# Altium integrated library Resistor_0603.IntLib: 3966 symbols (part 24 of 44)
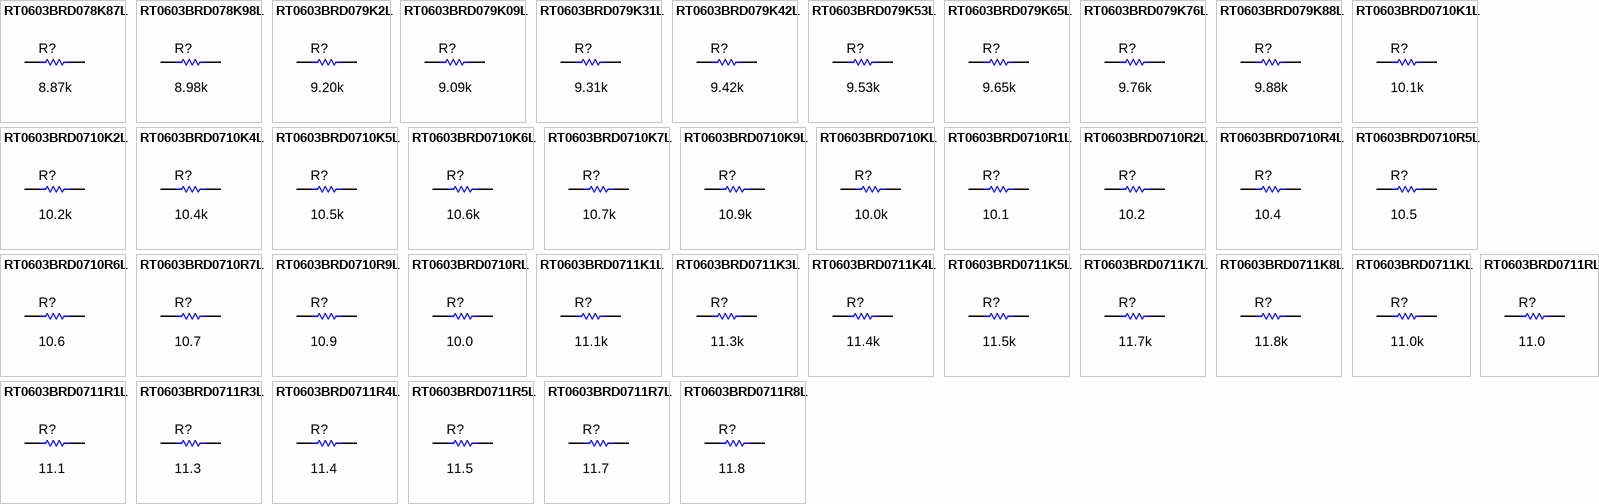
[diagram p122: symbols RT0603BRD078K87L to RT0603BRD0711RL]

## RT0603BRD078K87L
designator R?  ValueDisplayed: 8.87k  (hidden comment: RT0603BRD078K87L)
RES, 8.87 k, 0.1%, 0.1 W, 0603; Manufacturer: Yageo America; CompType: Resistor; Value: 8.87k; Res_ohm: 8870; Value_Code: 8k87; Tolerance_%: 0.1; Value2: 0.1W; VDC_V: 75; TempCo: 25 ppm/C; SizeArea_mm2: 1.28; SizeX_mm: 1.6; SizeY_mm: 0.8; SizeZ_mm: 1; EIA_Code: E192; U/M: EA; AEC Category: Q200
signal-integrity model Resistor
simulation model Resistor
footprint 0603
footprint 0603M
footprint 0603L
footprint 0603_HV
footprint 0603S
pins: 1, 2

## RT0603BRD078K98L
designator R?  ValueDisplayed: 8.98k  (hidden comment: RT0603BRD078K98L)
RES, 8.98 k, 0.1%, 0.1 W, 0603; Manufacturer: Yageo America; CompType: Resistor; Value: 8.98k; Res_ohm: 8980; Value_Code: 8k98; Tolerance_%: 0.1; Value2: 0.1W; VDC_V: 75; TempCo: 25 ppm/C; SizeArea_mm2: 1.28; SizeX_mm: 1.6; SizeY_mm: 0.8; SizeZ_mm: 1; EIA_Code: E192; U/M: EA; AEC Category: Q200
signal-integrity model Resistor
simulation model Resistor
footprint 0603
footprint 0603M
footprint 0603L
footprint 0603_HV
footprint 0603S
pins: 1, 2

## RT0603BRD079K2L
designator R?  ValueDisplayed: 9.20k  (hidden comment: RT0603BRD079K2L)
RES, 9.20 k, 0.1%, 0.1 W, 0603; Manufacturer: Yageo America; CompType: Resistor; Value: 9.20k; Res_ohm: 9200; Value_Code: 9k20; Tolerance_%: 0.1; Value2: 0.1W; VDC_V: 75; TempCo: 25 ppm/C; SizeArea_mm2: 1.28; SizeX_mm: 1.6; SizeY_mm: 0.8; SizeZ_mm: 1; EIA_Code: E192; U/M: EA; AEC Category: Q200
signal-integrity model Resistor
simulation model Resistor
footprint 0603
footprint 0603M
footprint 0603L
footprint 0603_HV
footprint 0603S
pins: 1, 2

## RT0603BRD079K09L
designator R?  ValueDisplayed: 9.09k  (hidden comment: RT0603BRD079K09L)
RES, 9.09 k, 0.1%, 0.1 W, 0603; Manufacturer: Yageo America; CompType: Resistor; Value: 9.09k; Res_ohm: 9090; Value_Code: 9k09; Tolerance_%: 0.1; Value2: 0.1W; VDC_V: 75; TempCo: 25 ppm/C; SizeArea_mm2: 1.28; SizeX_mm: 1.6; SizeY_mm: 0.8; SizeZ_mm: 1; EIA_Code: E192; U/M: EA; AEC Category: Q200
signal-integrity model Resistor
simulation model Resistor
footprint 0603
footprint 0603M
footprint 0603L
footprint 0603_HV
footprint 0603S
pins: 1, 2

## RT0603BRD079K31L
designator R?  ValueDisplayed: 9.31k  (hidden comment: RT0603BRD079K31L)
RES, 9.31 k, 0.1%, 0.1 W, 0603; Manufacturer: Yageo America; CompType: Resistor; Value: 9.31k; Res_ohm: 9310; Value_Code: 9k31; Tolerance_%: 0.1; Value2: 0.1W; VDC_V: 75; TempCo: 25 ppm/C; SizeArea_mm2: 1.28; SizeX_mm: 1.6; SizeY_mm: 0.8; SizeZ_mm: 1; EIA_Code: E192; U/M: EA; AEC Category: Q200
signal-integrity model Resistor
simulation model Resistor
footprint 0603
footprint 0603M
footprint 0603L
footprint 0603_HV
footprint 0603S
pins: 1, 2

## RT0603BRD079K42L
designator R?  ValueDisplayed: 9.42k  (hidden comment: RT0603BRD079K42L)
RES, 9.42 k, 0.1%, 0.1 W, 0603; Manufacturer: Yageo America; CompType: Resistor; Value: 9.42k; Res_ohm: 9420; Value_Code: 9k42; Tolerance_%: 0.1; Value2: 0.1W; VDC_V: 75; TempCo: 25 ppm/C; SizeArea_mm2: 1.28; SizeX_mm: 1.6; SizeY_mm: 0.8; SizeZ_mm: 1; EIA_Code: E192; U/M: EA; AEC Category: Q200
signal-integrity model Resistor
simulation model Resistor
footprint 0603
footprint 0603M
footprint 0603L
footprint 0603_HV
footprint 0603S
pins: 1, 2

## RT0603BRD079K53L
designator R?  ValueDisplayed: 9.53k  (hidden comment: RT0603BRD079K53L)
RES, 9.53 k, 0.1%, 0.1 W, 0603; Manufacturer: Yageo America; CompType: Resistor; Value: 9.53k; Res_ohm: 9530; Value_Code: 9k53; Tolerance_%: 0.1; Value2: 0.1W; VDC_V: 75; TempCo: 25 ppm/C; SizeArea_mm2: 1.28; SizeX_mm: 1.6; SizeY_mm: 0.8; SizeZ_mm: 1; EIA_Code: E192; U/M: EA; AEC Category: Q200
signal-integrity model Resistor
simulation model Resistor
footprint 0603
footprint 0603M
footprint 0603L
footprint 0603_HV
footprint 0603S
pins: 1, 2

## RT0603BRD079K65L
designator R?  ValueDisplayed: 9.65k  (hidden comment: RT0603BRD079K65L)
RES, 9.65 k, 0.1%, 0.1 W, 0603; Manufacturer: Yageo America; CompType: Resistor; Value: 9.65k; Res_ohm: 9650; Value_Code: 9k65; Tolerance_%: 0.1; Value2: 0.1W; VDC_V: 75; TempCo: 25 ppm/C; SizeArea_mm2: 1.28; SizeX_mm: 1.6; SizeY_mm: 0.8; SizeZ_mm: 1; EIA_Code: E192; U/M: EA; AEC Category: Q200
signal-integrity model Resistor
simulation model Resistor
footprint 0603
footprint 0603M
footprint 0603L
footprint 0603_HV
footprint 0603S
pins: 1, 2

## RT0603BRD079K76L
designator R?  ValueDisplayed: 9.76k  (hidden comment: RT0603BRD079K76L)
RES, 9.76 k, 0.1%, 0.1 W, 0603; Manufacturer: Yageo America; CompType: Resistor; Value: 9.76k; Res_ohm: 9760; Value_Code: 9k76; Tolerance_%: 0.1; Value2: 0.1W; VDC_V: 75; TempCo: 25 ppm/C; SizeArea_mm2: 1.28; SizeX_mm: 1.6; SizeY_mm: 0.8; SizeZ_mm: 1; EIA_Code: E192; U/M: EA; AEC Category: Q200
signal-integrity model Resistor
simulation model Resistor
footprint 0603
footprint 0603M
footprint 0603L
footprint 0603_HV
footprint 0603S
pins: 1, 2

## RT0603BRD079K88L
designator R?  ValueDisplayed: 9.88k  (hidden comment: RT0603BRD079K88L)
RES, 9.88 k, 0.1%, 0.1 W, 0603; Manufacturer: Yageo America; CompType: Resistor; Value: 9.88k; Res_ohm: 9880; Value_Code: 9k88; Tolerance_%: 0.1; Value2: 0.1W; VDC_V: 75; TempCo: 25 ppm/C; SizeArea_mm2: 1.28; SizeX_mm: 1.6; SizeY_mm: 0.8; SizeZ_mm: 1; EIA_Code: E192; U/M: EA; AEC Category: Q200
signal-integrity model Resistor
simulation model Resistor
footprint 0603
footprint 0603M
footprint 0603L
footprint 0603_HV
footprint 0603S
pins: 1, 2

## RT0603BRD0710K1L
designator R?  ValueDisplayed: 10.1k  (hidden comment: RT0603BRD0710K1L)
RES, 10.1 k, 0.1%, 0.1 W, 0603; Manufacturer: Yageo America; CompType: Resistor; Value: 10.1k; Res_ohm: 10100; Value_Code: 10k1; Tolerance_%: 0.1; Value2: 0.1W; VDC_V: 75; TempCo: 25 ppm/C; SizeArea_mm2: 1.28; SizeX_mm: 1.6; SizeY_mm: 0.8; SizeZ_mm: 1; EIA_Code: E192; U/M: EA; AEC Category: Q200
signal-integrity model Resistor
simulation model Resistor
footprint 0603
footprint 0603M
footprint 0603L
footprint 0603_HV
footprint 0603S
pins: 1, 2

## RT0603BRD0710K2L
designator R?  ValueDisplayed: 10.2k  (hidden comment: RT0603BRD0710K2L)
RES, 10.2 k, 0.1%, 0.1 W, 0603; Manufacturer: Yageo America; CompType: Resistor; Value: 10.2k; Res_ohm: 10200; Value_Code: 10k2; Tolerance_%: 0.1; Value2: 0.1W; VDC_V: 75; TempCo: 25 ppm/C; SizeArea_mm2: 1.28; SizeX_mm: 1.6; SizeY_mm: 0.8; SizeZ_mm: 1; EIA_Code: E192; U/M: EA; AEC Category: Q200
signal-integrity model Resistor
simulation model Resistor
footprint 0603
footprint 0603M
footprint 0603L
footprint 0603_HV
footprint 0603S
pins: 1, 2

## RT0603BRD0710K4L
designator R?  ValueDisplayed: 10.4k  (hidden comment: RT0603BRD0710K4L)
RES, 10.4 k, 0.1%, 0.1 W, 0603; Manufacturer: Yageo America; CompType: Resistor; Value: 10.4k; Res_ohm: 10400; Value_Code: 10k4; Tolerance_%: 0.1; Value2: 0.1W; VDC_V: 75; TempCo: 25 ppm/C; SizeArea_mm2: 1.28; SizeX_mm: 1.6; SizeY_mm: 0.8; SizeZ_mm: 1; EIA_Code: E192; U/M: EA; AEC Category: Q200
signal-integrity model Resistor
simulation model Resistor
footprint 0603
footprint 0603M
footprint 0603L
footprint 0603_HV
footprint 0603S
pins: 1, 2

## RT0603BRD0710K5L
designator R?  ValueDisplayed: 10.5k  (hidden comment: RT0603BRD0710K5L)
RES, 10.5 k, 0.1%, 0.1 W, 0603; Manufacturer: Yageo America; CompType: Resistor; Value: 10.5k; Res_ohm: 10500; Value_Code: 10k5; Tolerance_%: 0.1; Value2: 0.1W; VDC_V: 75; TempCo: 25 ppm/C; SizeArea_mm2: 1.28; SizeX_mm: 1.6; SizeY_mm: 0.8; SizeZ_mm: 1; EIA_Code: E192; U/M: EA; AEC Category: Q200
signal-integrity model Resistor
simulation model Resistor
footprint 0603
footprint 0603M
footprint 0603L
footprint 0603_HV
footprint 0603S
pins: 1, 2

## RT0603BRD0710K6L
designator R?  ValueDisplayed: 10.6k  (hidden comment: RT0603BRD0710K6L)
RES, 10.6 k, 0.1%, 0.1 W, 0603; Manufacturer: Yageo America; CompType: Resistor; Value: 10.6k; Res_ohm: 10600; Value_Code: 10k6; Tolerance_%: 0.1; Value2: 0.1W; VDC_V: 75; TempCo: 25 ppm/C; SizeArea_mm2: 1.28; SizeX_mm: 1.6; SizeY_mm: 0.8; SizeZ_mm: 1; EIA_Code: E192; U/M: EA; AEC Category: Q200
signal-integrity model Resistor
simulation model Resistor
footprint 0603
footprint 0603M
footprint 0603L
footprint 0603_HV
footprint 0603S
pins: 1, 2

## RT0603BRD0710K7L
designator R?  ValueDisplayed: 10.7k  (hidden comment: RT0603BRD0710K7L)
RES, 10.7 k, 0.1%, 0.1 W, 0603; Manufacturer: Yageo America; CompType: Resistor; Value: 10.7k; Res_ohm: 10700; Value_Code: 10k7; Tolerance_%: 0.1; Value2: 0.1W; VDC_V: 75; TempCo: 25 ppm/C; SizeArea_mm2: 1.28; SizeX_mm: 1.6; SizeY_mm: 0.8; SizeZ_mm: 1; EIA_Code: E192; U/M: EA; AEC Category: Q200
signal-integrity model Resistor
simulation model Resistor
footprint 0603
footprint 0603M
footprint 0603L
footprint 0603_HV
footprint 0603S
pins: 1, 2

## RT0603BRD0710K9L
designator R?  ValueDisplayed: 10.9k  (hidden comment: RT0603BRD0710K9L)
RES, 10.9 k, 0.1%, 0.1 W, 0603; Manufacturer: Yageo America; CompType: Resistor; Value: 10.9k; Res_ohm: 10900; Value_Code: 10k9; Tolerance_%: 0.1; Value2: 0.1W; VDC_V: 75; TempCo: 25 ppm/C; SizeArea_mm2: 1.28; SizeX_mm: 1.6; SizeY_mm: 0.8; SizeZ_mm: 1; EIA_Code: E192; U/M: EA; AEC Category: Q200
signal-integrity model Resistor
simulation model Resistor
footprint 0603
footprint 0603M
footprint 0603L
footprint 0603_HV
footprint 0603S
pins: 1, 2

## RT0603BRD0710KL
designator R?  ValueDisplayed: 10.0k  (hidden comment: RT0603BRD0710KL)
RES, 10.0 k, 0.1%, 0.1 W, 0603; Manufacturer: Yageo America; CompType: Resistor; Value: 10.0k; Res_ohm: 10000; Value_Code: 10k0; Tolerance_%: 0.1; Value2: 0.1W; VDC_V: 75; TempCo: 25 ppm/C; SizeArea_mm2: 1.28; SizeX_mm: 1.6; SizeY_mm: 0.8; SizeZ_mm: 1; EIA_Code: E192; U/M: EA; AEC Category: Q200; Green_Lifecycle: Active; Green_REACh: Passed
signal-integrity model Resistor
simulation model Resistor
footprint 0603
footprint 0603M
footprint 0603L
footprint 0603_HV
footprint 0603S
pins: 1, 2

## RT0603BRD0710R1L
designator R?  ValueDisplayed: 10.1  (hidden comment: RT0603BRD0710R1L)
RES, 10.1, 0.1%, 0.1 W, 0603; Manufacturer: Yageo America; CompType: Resistor; Value: 10.1; Value_Code: 10R1; Tolerance_%: 0.1; Value2: 0.1W; VDC_V: 75; TempCo: 25 ppm/C; SizeArea_mm2: 1.28; SizeX_mm: 1.6; SizeY_mm: 0.8; SizeZ_mm: 1; EIA_Code: E192; U/M: EA; AEC Category: Q200
signal-integrity model Resistor
simulation model Resistor
footprint 0603
footprint 0603M
footprint 0603L
footprint 0603_HV
footprint 0603S
pins: 1, 2

## RT0603BRD0710R2L
designator R?  ValueDisplayed: 10.2  (hidden comment: RT0603BRD0710R2L)
RES, 10.2, 0.1%, 0.1 W, 0603; Manufacturer: Yageo America; CompType: Resistor; Value: 10.2; Value_Code: 10R2; Tolerance_%: 0.1; Value2: 0.1W; VDC_V: 75; TempCo: 25 ppm/C; SizeArea_mm2: 1.28; SizeX_mm: 1.6; SizeY_mm: 0.8; SizeZ_mm: 1; EIA_Code: E192; U/M: EA; AEC Category: Q200
signal-integrity model Resistor
simulation model Resistor
footprint 0603
footprint 0603M
footprint 0603L
footprint 0603_HV
footprint 0603S
pins: 1, 2

## RT0603BRD0710R4L
designator R?  ValueDisplayed: 10.4  (hidden comment: RT0603BRD0710R4L)
RES, 10.4, 0.1%, 0.1 W, 0603; Manufacturer: Yageo America; CompType: Resistor; Value: 10.4; Value_Code: 10R4; Tolerance_%: 0.1; Value2: 0.1W; VDC_V: 75; TempCo: 25 ppm/C; SizeArea_mm2: 1.28; SizeX_mm: 1.6; SizeY_mm: 0.8; SizeZ_mm: 1; EIA_Code: E192; U/M: EA; AEC Category: Q200
signal-integrity model Resistor
simulation model Resistor
footprint 0603
footprint 0603M
footprint 0603L
footprint 0603_HV
footprint 0603S
pins: 1, 2

## RT0603BRD0710R5L
designator R?  ValueDisplayed: 10.5  (hidden comment: RT0603BRD0710R5L)
RES, 10.5, 0.1%, 0.1 W, 0603; Manufacturer: Yageo America; CompType: Resistor; Value: 10.5; Value_Code: 10R5; Tolerance_%: 0.1; Value2: 0.1W; VDC_V: 75; TempCo: 25 ppm/C; SizeArea_mm2: 1.28; SizeX_mm: 1.6; SizeY_mm: 0.8; SizeZ_mm: 1; EIA_Code: E192; U/M: EA; AEC Category: Q200
signal-integrity model Resistor
simulation model Resistor
footprint 0603
footprint 0603M
footprint 0603L
footprint 0603_HV
footprint 0603S
pins: 1, 2

## RT0603BRD0710R6L
designator R?  ValueDisplayed: 10.6  (hidden comment: RT0603BRD0710R6L)
RES, 10.6, 0.1%, 0.1 W, 0603; Manufacturer: Yageo America; CompType: Resistor; Value: 10.6; Value_Code: 10R6; Tolerance_%: 0.1; Value2: 0.1W; VDC_V: 75; TempCo: 25 ppm/C; SizeArea_mm2: 1.28; SizeX_mm: 1.6; SizeY_mm: 0.8; SizeZ_mm: 1; EIA_Code: E192; U/M: EA; AEC Category: Q200
signal-integrity model Resistor
simulation model Resistor
footprint 0603
footprint 0603M
footprint 0603L
footprint 0603_HV
footprint 0603S
pins: 1, 2

## RT0603BRD0710R7L
designator R?  ValueDisplayed: 10.7  (hidden comment: RT0603BRD0710R7L)
RES, 10.7, 0.1%, 0.1 W, 0603; Manufacturer: Yageo America; CompType: Resistor; Value: 10.7; Value_Code: 10R7; Tolerance_%: 0.1; Value2: 0.1W; VDC_V: 75; TempCo: 25 ppm/C; SizeArea_mm2: 1.28; SizeX_mm: 1.6; SizeY_mm: 0.8; SizeZ_mm: 1; EIA_Code: E192; U/M: EA; AEC Category: Q200
signal-integrity model Resistor
simulation model Resistor
footprint 0603
footprint 0603M
footprint 0603L
footprint 0603_HV
footprint 0603S
pins: 1, 2

## RT0603BRD0710R9L
designator R?  ValueDisplayed: 10.9  (hidden comment: RT0603BRD0710R9L)
RES, 10.9, 0.1%, 0.1 W, 0603; Manufacturer: Yageo America; CompType: Resistor; Value: 10.9; Value_Code: 10R9; Tolerance_%: 0.1; Value2: 0.1W; VDC_V: 75; TempCo: 25 ppm/C; SizeArea_mm2: 1.28; SizeX_mm: 1.6; SizeY_mm: 0.8; SizeZ_mm: 1; EIA_Code: E192; U/M: EA; AEC Category: Q200
signal-integrity model Resistor
simulation model Resistor
footprint 0603
footprint 0603M
footprint 0603L
footprint 0603_HV
footprint 0603S
pins: 1, 2

## RT0603BRD0710RL
designator R?  ValueDisplayed: 10.0  (hidden comment: RT0603BRD0710RL)
RES, 10.0, 0.1%, 0.1 W, 0603; Manufacturer: Yageo America; CompType: Resistor; Value: 10.0; Res_ohm: 10; Value_Code: 10R0; Tolerance_%: 0.1; Value2: 0.1W; VDC_V: 75; TempCo: 25 ppm/C; SizeArea_mm2: 1.28; SizeX_mm: 1.6; SizeY_mm: 0.8; SizeZ_mm: 1; EIA_Code: E192; U/M: EA; AEC Category: Q200; Green_Lifecycle: Active; Green_REACh: Passed
signal-integrity model Resistor
simulation model Resistor
footprint 0603
footprint 0603M
footprint 0603L
footprint 0603_HV
footprint 0603S
pins: 1, 2

## RT0603BRD0711K1L
designator R?  ValueDisplayed: 11.1k  (hidden comment: RT0603BRD0711K1L)
RES, 11.1 k, 0.1%, 0.1 W, 0603; Manufacturer: Yageo America; CompType: Resistor; Value: 11.1k; Res_ohm: 11100; Value_Code: 11k1; Tolerance_%: 0.1; Value2: 0.1W; VDC_V: 75; TempCo: 25 ppm/C; SizeArea_mm2: 1.28; SizeX_mm: 1.6; SizeY_mm: 0.8; SizeZ_mm: 1; EIA_Code: E192; U/M: EA; AEC Category: Q200
signal-integrity model Resistor
simulation model Resistor
footprint 0603
footprint 0603M
footprint 0603L
footprint 0603_HV
footprint 0603S
pins: 1, 2

## RT0603BRD0711K3L
designator R?  ValueDisplayed: 11.3k  (hidden comment: RT0603BRD0711K3L)
RES, 11.3 k, 0.1%, 0.1 W, 0603; Manufacturer: Yageo America; CompType: Resistor; Value: 11.3k; Res_ohm: 11300; Value_Code: 11k3; Tolerance_%: 0.1; Value2: 0.1W; VDC_V: 75; TempCo: 25 ppm/C; SizeArea_mm2: 1.28; SizeX_mm: 1.6; SizeY_mm: 0.8; SizeZ_mm: 1; EIA_Code: E192; U/M: EA; AEC Category: Q200
signal-integrity model Resistor
simulation model Resistor
footprint 0603
footprint 0603M
footprint 0603L
footprint 0603_HV
footprint 0603S
pins: 1, 2

## RT0603BRD0711K4L
designator R?  ValueDisplayed: 11.4k  (hidden comment: RT0603BRD0711K4L)
RES, 11.4 k, 0.1%, 0.1 W, 0603; Manufacturer: Yageo America; CompType: Resistor; Value: 11.4k; Res_ohm: 11400; Value_Code: 11k4; Tolerance_%: 0.1; Value2: 0.1W; VDC_V: 75; TempCo: 25 ppm/C; SizeArea_mm2: 1.28; SizeX_mm: 1.6; SizeY_mm: 0.8; SizeZ_mm: 1; EIA_Code: E192; U/M: EA; AEC Category: Q200
signal-integrity model Resistor
simulation model Resistor
footprint 0603
footprint 0603M
footprint 0603L
footprint 0603_HV
footprint 0603S
pins: 1, 2

## RT0603BRD0711K5L
designator R?  ValueDisplayed: 11.5k  (hidden comment: RT0603BRD0711K5L)
RES, 11.5 k, 0.1%, 0.1 W, 0603; Manufacturer: Yageo America; CompType: Resistor; Value: 11.5k; Res_ohm: 11500; Value_Code: 11k5; Tolerance_%: 0.1; Value2: 0.1W; VDC_V: 75; TempCo: 25 ppm/C; SizeArea_mm2: 1.28; SizeX_mm: 1.6; SizeY_mm: 0.8; SizeZ_mm: 1; EIA_Code: E192; U/M: EA; AEC Category: Q200
signal-integrity model Resistor
simulation model Resistor
footprint 0603
footprint 0603M
footprint 0603L
footprint 0603_HV
footprint 0603S
pins: 1, 2

## RT0603BRD0711K7L
designator R?  ValueDisplayed: 11.7k  (hidden comment: RT0603BRD0711K7L)
RES, 11.7 k, 0.1%, 0.1 W, 0603; Manufacturer: Yageo America; CompType: Resistor; Value: 11.7k; Res_ohm: 11700; Value_Code: 11k7; Tolerance_%: 0.1; Value2: 0.1W; VDC_V: 75; TempCo: 25 ppm/C; SizeArea_mm2: 1.28; SizeX_mm: 1.6; SizeY_mm: 0.8; SizeZ_mm: 1; EIA_Code: E192; U/M: EA; AEC Category: Q200
signal-integrity model Resistor
simulation model Resistor
footprint 0603
footprint 0603M
footprint 0603L
footprint 0603_HV
footprint 0603S
pins: 1, 2

## RT0603BRD0711K8L
designator R?  ValueDisplayed: 11.8k  (hidden comment: RT0603BRD0711K8L)
RES, 11.8 k, 0.1%, 0.1 W, 0603; Manufacturer: Yageo America; CompType: Resistor; Value: 11.8k; Res_ohm: 11800; Value_Code: 11k8; Tolerance_%: 0.1; Value2: 0.1W; VDC_V: 75; TempCo: 25 ppm/C; SizeArea_mm2: 1.28; SizeX_mm: 1.6; SizeY_mm: 0.8; SizeZ_mm: 1; EIA_Code: E192; U/M: EA; AEC Category: Q200
signal-integrity model Resistor
simulation model Resistor
footprint 0603
footprint 0603M
footprint 0603L
footprint 0603_HV
footprint 0603S
pins: 1, 2

## RT0603BRD0711KL
designator R?  ValueDisplayed: 11.0k  (hidden comment: RT0603BRD0711KL)
RES, 11.0 k, 0.1%, 0.1 W, 0603; Manufacturer: Yageo America; CompType: Resistor; Value: 11.0k; Res_ohm: 11000; Value_Code: 11k0; Tolerance_%: 0.1; Value2: 0.1W; VDC_V: 75; TempCo: 25 ppm/C; SizeArea_mm2: 1.28; SizeX_mm: 1.6; SizeY_mm: 0.8; SizeZ_mm: 1; EIA_Code: E192; U/M: EA; AEC Category: Q200
signal-integrity model Resistor
simulation model Resistor
footprint 0603
footprint 0603M
footprint 0603L
footprint 0603_HV
footprint 0603S
pins: 1, 2

## RT0603BRD0711R1L
designator R?  ValueDisplayed: 11.1  (hidden comment: RT0603BRD0711R1L)
RES, 11.1, 0.1%, 0.1 W, 0603; Manufacturer: Yageo America; CompType: Resistor; Value: 11.1; Value_Code: 11R1; Tolerance_%: 0.1; Value2: 0.1W; VDC_V: 75; TempCo: 25 ppm/C; SizeArea_mm2: 1.28; SizeX_mm: 1.6; SizeY_mm: 0.8; SizeZ_mm: 1; EIA_Code: E192; U/M: EA; AEC Category: Q200
signal-integrity model Resistor
simulation model Resistor
footprint 0603
footprint 0603M
footprint 0603L
footprint 0603_HV
footprint 0603S
pins: 1, 2

## RT0603BRD0711R3L
designator R?  ValueDisplayed: 11.3  (hidden comment: RT0603BRD0711R3L)
RES, 11.3, 0.1%, 0.1 W, 0603; Manufacturer: Yageo America; CompType: Resistor; Value: 11.3; Value_Code: 11R3; Tolerance_%: 0.1; Value2: 0.1W; VDC_V: 75; TempCo: 25 ppm/C; SizeArea_mm2: 1.28; SizeX_mm: 1.6; SizeY_mm: 0.8; SizeZ_mm: 1; EIA_Code: E192; U/M: EA; AEC Category: Q200
signal-integrity model Resistor
simulation model Resistor
footprint 0603
footprint 0603M
footprint 0603L
footprint 0603_HV
footprint 0603S
pins: 1, 2

## RT0603BRD0711R4L
designator R?  ValueDisplayed: 11.4  (hidden comment: RT0603BRD0711R4L)
RES, 11.4, 0.1%, 0.1 W, 0603; Manufacturer: Yageo America; CompType: Resistor; Value: 11.4; Value_Code: 11R4; Tolerance_%: 0.1; Value2: 0.1W; VDC_V: 75; TempCo: 25 ppm/C; SizeArea_mm2: 1.28; SizeX_mm: 1.6; SizeY_mm: 0.8; SizeZ_mm: 1; EIA_Code: E192; U/M: EA; AEC Category: Q200
signal-integrity model Resistor
simulation model Resistor
footprint 0603
footprint 0603M
footprint 0603L
footprint 0603_HV
footprint 0603S
pins: 1, 2

## RT0603BRD0711R5L
designator R?  ValueDisplayed: 11.5  (hidden comment: RT0603BRD0711R5L)
RES, 11.5, 0.1%, 0.1 W, 0603; Manufacturer: Yageo America; CompType: Resistor; Value: 11.5; Value_Code: 11R5; Tolerance_%: 0.1; Value2: 0.1W; VDC_V: 75; TempCo: 25 ppm/C; SizeArea_mm2: 1.28; SizeX_mm: 1.6; SizeY_mm: 0.8; SizeZ_mm: 1; EIA_Code: E192; U/M: EA; AEC Category: Q200
signal-integrity model Resistor
simulation model Resistor
footprint 0603
footprint 0603M
footprint 0603L
footprint 0603_HV
footprint 0603S
pins: 1, 2

## RT0603BRD0711R7L
designator R?  ValueDisplayed: 11.7  (hidden comment: RT0603BRD0711R7L)
RES, 11.7, 0.1%, 0.1 W, 0603; Manufacturer: Yageo America; CompType: Resistor; Value: 11.7; Value_Code: 11R7; Tolerance_%: 0.1; Value2: 0.1W; VDC_V: 75; TempCo: 25 ppm/C; SizeArea_mm2: 1.28; SizeX_mm: 1.6; SizeY_mm: 0.8; SizeZ_mm: 1; EIA_Code: E192; U/M: EA; AEC Category: Q200
signal-integrity model Resistor
simulation model Resistor
footprint 0603
footprint 0603M
footprint 0603L
footprint 0603_HV
footprint 0603S
pins: 1, 2

## RT0603BRD0711R8L
designator R?  ValueDisplayed: 11.8  (hidden comment: RT0603BRD0711R8L)
RES, 11.8, 0.1%, 0.1 W, 0603; Manufacturer: Yageo America; CompType: Resistor; Value: 11.8; Value_Code: 11R8; Tolerance_%: 0.1; Value2: 0.1W; VDC_V: 75; TempCo: 25 ppm/C; SizeArea_mm2: 1.28; SizeX_mm: 1.6; SizeY_mm: 0.8; SizeZ_mm: 1; EIA_Code: E192; U/M: EA; AEC Category: Q200
signal-integrity model Resistor
simulation model Resistor
footprint 0603
footprint 0603M
footprint 0603L
footprint 0603_HV
footprint 0603S
pins: 1, 2

## RT0603BRD0711RL
designator R?  ValueDisplayed: 11.0  (hidden comment: RT0603BRD0711RL)
RES, 11.0, 0.1%, 0.1 W, 0603; Manufacturer: Yageo America; CompType: Resistor; Value: 11.0; Res_ohm: 11; Value_Code: 11R0; Tolerance_%: 0.1; Value2: 0.1W; VDC_V: 75; TempCo: 25 ppm/C; SizeArea_mm2: 1.28; SizeX_mm: 1.6; SizeY_mm: 0.8; SizeZ_mm: 1; EIA_Code: E192; U/M: EA; AEC Category: Q200
signal-integrity model Resistor
simulation model Resistor
footprint 0603
footprint 0603M
footprint 0603L
footprint 0603_HV
footprint 0603S
pins: 1, 2

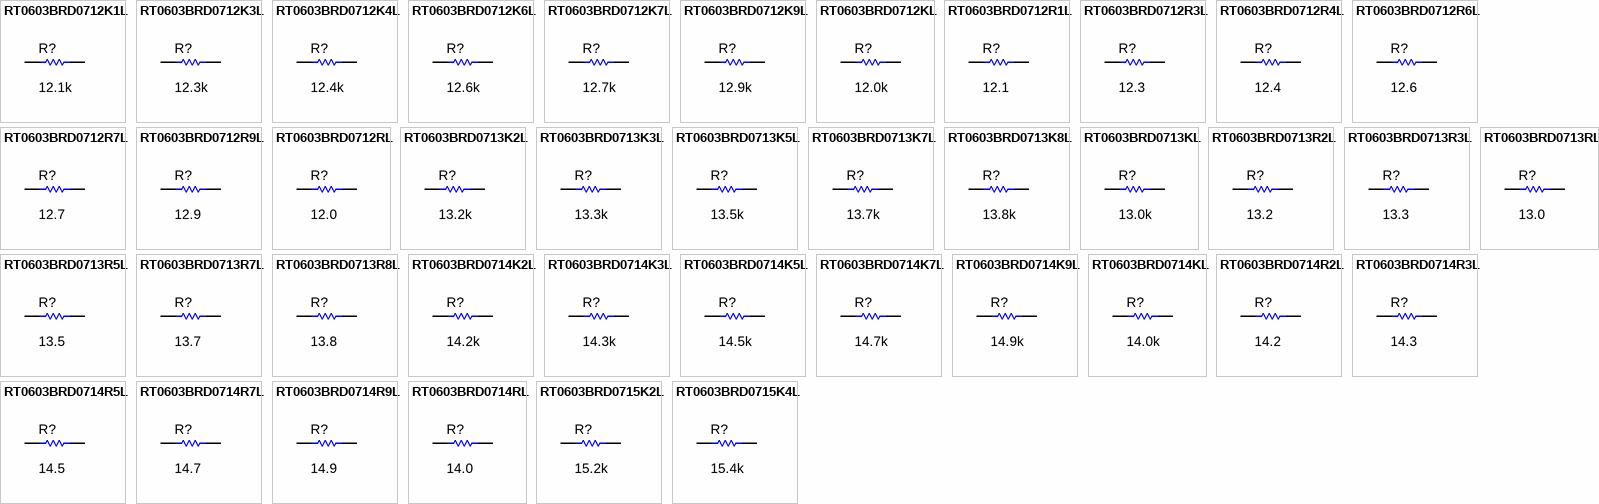
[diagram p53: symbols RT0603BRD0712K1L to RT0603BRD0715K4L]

## RT0603BRD0712K1L
designator R?  ValueDisplayed: 12.1k  (hidden comment: RT0603BRD0712K1L)
RES, 12.1 k, 0.1%, 0.1 W, 0603; Manufacturer: Yageo America; CompType: Resistor; Value: 12.1k; Res_ohm: 12100; Value_Code: 12k1; Tolerance_%: 0.1; Value2: 0.1W; VDC_V: 75; TempCo: 25 ppm/C; SizeArea_mm2: 1.28; SizeX_mm: 1.6; SizeY_mm: 0.8; SizeZ_mm: 1; EIA_Code: E192; U/M: EA; AEC Category: Q200
signal-integrity model Resistor
simulation model Resistor
footprint 0603
footprint 0603M
footprint 0603L
footprint 0603_HV
footprint 0603S
pins: 1, 2

## RT0603BRD0712K3L
designator R?  ValueDisplayed: 12.3k  (hidden comment: RT0603BRD0712K3L)
RES, 12.3 k, 0.1%, 0.1 W, 0603; Manufacturer: Yageo America; CompType: Resistor; Value: 12.3k; Res_ohm: 12300; Value_Code: 12k3; Tolerance_%: 0.1; Value2: 0.1W; VDC_V: 75; TempCo: 25 ppm/C; SizeArea_mm2: 1.28; SizeX_mm: 1.6; SizeY_mm: 0.8; SizeZ_mm: 1; EIA_Code: E192; U/M: EA; AEC Category: Q200
signal-integrity model Resistor
simulation model Resistor
footprint 0603
footprint 0603M
footprint 0603L
footprint 0603_HV
footprint 0603S
pins: 1, 2

## RT0603BRD0712K4L
designator R?  ValueDisplayed: 12.4k  (hidden comment: RT0603BRD0712K4L)
RES, 12.4 k, 0.1%, 0.1 W, 0603; Manufacturer: Yageo America; CompType: Resistor; Value: 12.4k; Res_ohm: 12400; Value_Code: 12k4; Tolerance_%: 0.1; Value2: 0.1W; VDC_V: 75; TempCo: 25 ppm/C; SizeArea_mm2: 1.28; SizeX_mm: 1.6; SizeY_mm: 0.8; SizeZ_mm: 1; EIA_Code: E192; U/M: EA; AEC Category: Q200
signal-integrity model Resistor
simulation model Resistor
footprint 0603
footprint 0603M
footprint 0603L
footprint 0603_HV
footprint 0603S
pins: 1, 2

## RT0603BRD0712K6L
designator R?  ValueDisplayed: 12.6k  (hidden comment: RT0603BRD0712K6L)
RES, 12.6 k, 0.1%, 0.1 W, 0603; Manufacturer: Yageo America; CompType: Resistor; Value: 12.6k; Res_ohm: 12600; Value_Code: 12k6; Tolerance_%: 0.1; Value2: 0.1W; VDC_V: 75; TempCo: 25 ppm/C; SizeArea_mm2: 1.28; SizeX_mm: 1.6; SizeY_mm: 0.8; SizeZ_mm: 1; EIA_Code: E192; U/M: EA; AEC Category: Q200
signal-integrity model Resistor
simulation model Resistor
footprint 0603
footprint 0603M
footprint 0603L
footprint 0603_HV
footprint 0603S
pins: 1, 2

## RT0603BRD0712K7L
designator R?  ValueDisplayed: 12.7k  (hidden comment: RT0603BRD0712K7L)
RES, 12.7 k, 0.1%, 0.1 W, 0603; Manufacturer: Yageo America; CompType: Resistor; Value: 12.7k; Res_ohm: 12700; Value_Code: 12k7; Tolerance_%: 0.1; Value2: 0.1W; VDC_V: 75; TempCo: 25 ppm/C; SizeArea_mm2: 1.28; SizeX_mm: 1.6; SizeY_mm: 0.8; SizeZ_mm: 1; EIA_Code: E192; U/M: EA; AEC Category: Q200
signal-integrity model Resistor
simulation model Resistor
footprint 0603
footprint 0603M
footprint 0603L
footprint 0603_HV
footprint 0603S
pins: 1, 2

## RT0603BRD0712K9L
designator R?  ValueDisplayed: 12.9k  (hidden comment: RT0603BRD0712K9L)
RES, 12.9 k, 0.1%, 0.1 W, 0603; Manufacturer: Yageo America; CompType: Resistor; Value: 12.9k; Res_ohm: 12900; Value_Code: 12k9; Tolerance_%: 0.1; Value2: 0.1W; VDC_V: 75; TempCo: 25 ppm/C; SizeArea_mm2: 1.28; SizeX_mm: 1.6; SizeY_mm: 0.8; SizeZ_mm: 1; EIA_Code: E192; U/M: EA; AEC Category: Q200
signal-integrity model Resistor
simulation model Resistor
footprint 0603
footprint 0603M
footprint 0603L
footprint 0603_HV
footprint 0603S
pins: 1, 2

## RT0603BRD0712KL
designator R?  ValueDisplayed: 12.0k  (hidden comment: RT0603BRD0712KL)
RES, 12.0 k, 0.1%, 0.1 W, 0603; Manufacturer: Yageo America; CompType: Resistor; Value: 12.0k; Res_ohm: 12000; Value_Code: 12k0; Tolerance_%: 0.1; Value2: 0.1W; VDC_V: 75; TempCo: 25 ppm/C; SizeArea_mm2: 1.28; SizeX_mm: 1.6; SizeY_mm: 0.8; SizeZ_mm: 1; EIA_Code: E192; U/M: EA; AEC Category: Q200
signal-integrity model Resistor
simulation model Resistor
footprint 0603
footprint 0603M
footprint 0603L
footprint 0603_HV
footprint 0603S
pins: 1, 2

## RT0603BRD0712R1L
designator R?  ValueDisplayed: 12.1  (hidden comment: RT0603BRD0712R1L)
RES, 12.1, 0.1%, 0.1 W, 0603; Manufacturer: Yageo America; CompType: Resistor; Value: 12.1; Value_Code: 12R1; Tolerance_%: 0.1; Value2: 0.1W; VDC_V: 75; TempCo: 25 ppm/C; SizeArea_mm2: 1.28; SizeX_mm: 1.6; SizeY_mm: 0.8; SizeZ_mm: 1; EIA_Code: E192; U/M: EA; AEC Category: Q200
signal-integrity model Resistor
simulation model Resistor
footprint 0603
footprint 0603M
footprint 0603L
footprint 0603_HV
footprint 0603S
pins: 1, 2

## RT0603BRD0712R3L
designator R?  ValueDisplayed: 12.3  (hidden comment: RT0603BRD0712R3L)
RES, 12.3, 0.1%, 0.1 W, 0603; Manufacturer: Yageo America; CompType: Resistor; Value: 12.3; Value_Code: 12R3; Tolerance_%: 0.1; Value2: 0.1W; VDC_V: 75; TempCo: 25 ppm/C; SizeArea_mm2: 1.28; SizeX_mm: 1.6; SizeY_mm: 0.8; SizeZ_mm: 1; EIA_Code: E192; U/M: EA; AEC Category: Q200
signal-integrity model Resistor
simulation model Resistor
footprint 0603
footprint 0603M
footprint 0603L
footprint 0603_HV
footprint 0603S
pins: 1, 2

## RT0603BRD0712R4L
designator R?  ValueDisplayed: 12.4  (hidden comment: RT0603BRD0712R4L)
RES, 12.4, 0.1%, 0.1 W, 0603; Manufacturer: Yageo America; CompType: Resistor; Value: 12.4; Value_Code: 12R4; Tolerance_%: 0.1; Value2: 0.1W; VDC_V: 75; TempCo: 25 ppm/C; SizeArea_mm2: 1.28; SizeX_mm: 1.6; SizeY_mm: 0.8; SizeZ_mm: 1; EIA_Code: E192; U/M: EA; AEC Category: Q200
signal-integrity model Resistor
simulation model Resistor
footprint 0603
footprint 0603M
footprint 0603L
footprint 0603_HV
footprint 0603S
pins: 1, 2

## RT0603BRD0712R6L
designator R?  ValueDisplayed: 12.6  (hidden comment: RT0603BRD0712R6L)
RES, 12.6, 0.1%, 0.1 W, 0603; Manufacturer: Yageo America; CompType: Resistor; Value: 12.6; Value_Code: 12R6; Tolerance_%: 0.1; Value2: 0.1W; VDC_V: 75; TempCo: 25 ppm/C; SizeArea_mm2: 1.28; SizeX_mm: 1.6; SizeY_mm: 0.8; SizeZ_mm: 1; EIA_Code: E192; U/M: EA; AEC Category: Q200
signal-integrity model Resistor
simulation model Resistor
footprint 0603
footprint 0603M
footprint 0603L
footprint 0603_HV
footprint 0603S
pins: 1, 2

## RT0603BRD0712R7L
designator R?  ValueDisplayed: 12.7  (hidden comment: RT0603BRD0712R7L)
RES, 12.7, 0.1%, 0.1 W, 0603; Manufacturer: Yageo America; CompType: Resistor; Value: 12.7; Value_Code: 12R7; Tolerance_%: 0.1; Value2: 0.1W; VDC_V: 75; TempCo: 25 ppm/C; SizeArea_mm2: 1.28; SizeX_mm: 1.6; SizeY_mm: 0.8; SizeZ_mm: 1; EIA_Code: E192; U/M: EA; AEC Category: Q200
signal-integrity model Resistor
simulation model Resistor
footprint 0603
footprint 0603M
footprint 0603L
footprint 0603_HV
footprint 0603S
pins: 1, 2

## RT0603BRD0712R9L
designator R?  ValueDisplayed: 12.9  (hidden comment: RT0603BRD0712R9L)
RES, 12.9, 0.1%, 0.1 W, 0603; Manufacturer: Yageo America; CompType: Resistor; Value: 12.9; Value_Code: 12R9; Tolerance_%: 0.1; Value2: 0.1W; VDC_V: 75; TempCo: 25 ppm/C; SizeArea_mm2: 1.28; SizeX_mm: 1.6; SizeY_mm: 0.8; SizeZ_mm: 1; EIA_Code: E192; U/M: EA; AEC Category: Q200
signal-integrity model Resistor
simulation model Resistor
footprint 0603
footprint 0603M
footprint 0603L
footprint 0603_HV
footprint 0603S
pins: 1, 2

## RT0603BRD0712RL
designator R?  ValueDisplayed: 12.0  (hidden comment: RT0603BRD0712RL)
RES, 12.0, 0.1%, 0.1 W, 0603; Manufacturer: Yageo America; CompType: Resistor; Value: 12.0; Res_ohm: 12; Value_Code: 12R0; Tolerance_%: 0.1; Value2: 0.1W; VDC_V: 75; TempCo: 25 ppm/C; SizeArea_mm2: 1.28; SizeX_mm: 1.6; SizeY_mm: 0.8; SizeZ_mm: 1; EIA_Code: E192; U/M: EA; AEC Category: Q200
signal-integrity model Resistor
simulation model Resistor
footprint 0603
footprint 0603M
footprint 0603L
footprint 0603_HV
footprint 0603S
pins: 1, 2

## RT0603BRD0713K2L
designator R?  ValueDisplayed: 13.2k  (hidden comment: RT0603BRD0713K2L)
RES, 13.2 k, 0.1%, 0.1 W, 0603; Manufacturer: Yageo America; CompType: Resistor; Value: 13.2k; Res_ohm: 13200; Value_Code: 13k2; Tolerance_%: 0.1; Value2: 0.1W; VDC_V: 75; TempCo: 25 ppm/C; SizeArea_mm2: 1.28; SizeX_mm: 1.6; SizeY_mm: 0.8; SizeZ_mm: 1; EIA_Code: E192; U/M: EA; AEC Category: Q200
signal-integrity model Resistor
simulation model Resistor
footprint 0603
footprint 0603M
footprint 0603L
footprint 0603_HV
footprint 0603S
pins: 1, 2

## RT0603BRD0713K3L
designator R?  ValueDisplayed: 13.3k  (hidden comment: RT0603BRD0713K3L)
RES, 13.3 k, 0.1%, 0.1 W, 0603; Manufacturer: Yageo America; CompType: Resistor; Value: 13.3k; Res_ohm: 13300; Value_Code: 13k3; Tolerance_%: 0.1; Value2: 0.1W; VDC_V: 75; TempCo: 25 ppm/C; SizeArea_mm2: 1.28; SizeX_mm: 1.6; SizeY_mm: 0.8; SizeZ_mm: 1; EIA_Code: E192; U/M: EA; AEC Category: Q200
signal-integrity model Resistor
simulation model Resistor
footprint 0603
footprint 0603M
footprint 0603L
footprint 0603_HV
footprint 0603S
pins: 1, 2

## RT0603BRD0713K5L
designator R?  ValueDisplayed: 13.5k  (hidden comment: RT0603BRD0713K5L)
RES, 13.5 k, 0.1%, 0.1 W, 0603; Manufacturer: Yageo America; CompType: Resistor; Value: 13.5k; Res_ohm: 13500; Value_Code: 13k5; Tolerance_%: 0.1; Value2: 0.1W; VDC_V: 75; TempCo: 25 ppm/C; SizeArea_mm2: 1.28; SizeX_mm: 1.6; SizeY_mm: 0.8; SizeZ_mm: 1; EIA_Code: E192; U/M: EA; AEC Category: Q200
signal-integrity model Resistor
simulation model Resistor
footprint 0603
footprint 0603M
footprint 0603L
footprint 0603_HV
footprint 0603S
pins: 1, 2

## RT0603BRD0713K7L
designator R?  ValueDisplayed: 13.7k  (hidden comment: RT0603BRD0713K7L)
RES, 13.7 k, 0.1%, 0.1 W, 0603; Manufacturer: Yageo America; CompType: Resistor; Value: 13.7k; Res_ohm: 13700; Value_Code: 13k7; Tolerance_%: 0.1; Value2: 0.1W; VDC_V: 75; TempCo: 25 ppm/C; SizeArea_mm2: 1.28; SizeX_mm: 1.6; SizeY_mm: 0.8; SizeZ_mm: 1; EIA_Code: E192; U/M: EA; AEC Category: Q200
signal-integrity model Resistor
simulation model Resistor
footprint 0603
footprint 0603M
footprint 0603L
footprint 0603_HV
footprint 0603S
pins: 1, 2

## RT0603BRD0713K8L
designator R?  ValueDisplayed: 13.8k  (hidden comment: RT0603BRD0713K8L)
RES, 13.8 k, 0.1%, 0.1 W, 0603; Manufacturer: Yageo America; CompType: Resistor; Value: 13.8k; Res_ohm: 13800; Value_Code: 13k8; Tolerance_%: 0.1; Value2: 0.1W; VDC_V: 75; TempCo: 25 ppm/C; SizeArea_mm2: 1.28; SizeX_mm: 1.6; SizeY_mm: 0.8; SizeZ_mm: 1; EIA_Code: E192; U/M: EA; AEC Category: Q200
signal-integrity model Resistor
simulation model Resistor
footprint 0603
footprint 0603M
footprint 0603L
footprint 0603_HV
footprint 0603S
pins: 1, 2

## RT0603BRD0713KL
designator R?  ValueDisplayed: 13.0k  (hidden comment: RT0603BRD0713KL)
RES, 13.0 k, 0.1%, 0.1 W, 0603; Manufacturer: Yageo America; CompType: Resistor; Value: 13.0k; Res_ohm: 13000; Value_Code: 13k0; Tolerance_%: 0.1; Value2: 0.1W; VDC_V: 75; TempCo: 25 ppm/C; SizeArea_mm2: 1.28; SizeX_mm: 1.6; SizeY_mm: 0.8; SizeZ_mm: 1; EIA_Code: E192; U/M: EA; AEC Category: Q200
signal-integrity model Resistor
simulation model Resistor
footprint 0603
footprint 0603M
footprint 0603L
footprint 0603_HV
footprint 0603S
pins: 1, 2

## RT0603BRD0713R2L
designator R?  ValueDisplayed: 13.2  (hidden comment: RT0603BRD0713R2L)
RES, 13.2, 0.1%, 0.1 W, 0603; Manufacturer: Yageo America; CompType: Resistor; Value: 13.2; Value_Code: 13R2; Tolerance_%: 0.1; Value2: 0.1W; VDC_V: 75; TempCo: 25 ppm/C; SizeArea_mm2: 1.28; SizeX_mm: 1.6; SizeY_mm: 0.8; SizeZ_mm: 1; EIA_Code: E192; U/M: EA; AEC Category: Q200
signal-integrity model Resistor
simulation model Resistor
footprint 0603
footprint 0603M
footprint 0603L
footprint 0603_HV
footprint 0603S
pins: 1, 2

## RT0603BRD0713R3L
designator R?  ValueDisplayed: 13.3  (hidden comment: RT0603BRD0713R3L)
RES, 13.3, 0.1%, 0.1 W, 0603; Manufacturer: Yageo America; CompType: Resistor; Value: 13.3; Value_Code: 13R3; Tolerance_%: 0.1; Value2: 0.1W; VDC_V: 75; TempCo: 25 ppm/C; SizeArea_mm2: 1.28; SizeX_mm: 1.6; SizeY_mm: 0.8; SizeZ_mm: 1; EIA_Code: E192; U/M: EA; AEC Category: Q200
signal-integrity model Resistor
simulation model Resistor
footprint 0603
footprint 0603M
footprint 0603L
footprint 0603_HV
footprint 0603S
pins: 1, 2

## RT0603BRD0713R5L
designator R?  ValueDisplayed: 13.5  (hidden comment: RT0603BRD0713R5L)
RES, 13.5, 0.1%, 0.1 W, 0603; Manufacturer: Yageo America; CompType: Resistor; Value: 13.5; Value_Code: 13R5; Tolerance_%: 0.1; Value2: 0.1W; VDC_V: 75; TempCo: 25 ppm/C; SizeArea_mm2: 1.28; SizeX_mm: 1.6; SizeY_mm: 0.8; SizeZ_mm: 1; EIA_Code: E192; U/M: EA; AEC Category: Q200
signal-integrity model Resistor
simulation model Resistor
footprint 0603
footprint 0603M
footprint 0603L
footprint 0603_HV
footprint 0603S
pins: 1, 2

## RT0603BRD0713R7L
designator R?  ValueDisplayed: 13.7  (hidden comment: RT0603BRD0713R7L)
RES, 13.7, 0.1%, 0.1 W, 0603; Manufacturer: Yageo America; CompType: Resistor; Value: 13.7; Value_Code: 13R7; Tolerance_%: 0.1; Value2: 0.1W; VDC_V: 75; TempCo: 25 ppm/C; SizeArea_mm2: 1.28; SizeX_mm: 1.6; SizeY_mm: 0.8; SizeZ_mm: 1; EIA_Code: E192; U/M: EA; AEC Category: Q200
signal-integrity model Resistor
simulation model Resistor
footprint 0603
footprint 0603M
footprint 0603L
footprint 0603_HV
footprint 0603S
pins: 1, 2

## RT0603BRD0713R8L
designator R?  ValueDisplayed: 13.8  (hidden comment: RT0603BRD0713R8L)
RES, 13.8, 0.1%, 0.1 W, 0603; Manufacturer: Yageo America; CompType: Resistor; Value: 13.8; Value_Code: 13R8; Tolerance_%: 0.1; Value2: 0.1W; VDC_V: 75; TempCo: 25 ppm/C; SizeArea_mm2: 1.28; SizeX_mm: 1.6; SizeY_mm: 0.8; SizeZ_mm: 1; EIA_Code: E192; U/M: EA; AEC Category: Q200
signal-integrity model Resistor
simulation model Resistor
footprint 0603
footprint 0603M
footprint 0603L
footprint 0603_HV
footprint 0603S
pins: 1, 2

## RT0603BRD0713RL
designator R?  ValueDisplayed: 13.0  (hidden comment: RT0603BRD0713RL)
RES, 13.0, 0.1%, 0.1 W, 0603; Manufacturer: Yageo America; CompType: Resistor; Value: 13.0; Res_ohm: 13; Value_Code: 13R0; Tolerance_%: 0.1; Value2: 0.1W; VDC_V: 75; TempCo: 25 ppm/C; SizeArea_mm2: 1.28; SizeX_mm: 1.6; SizeY_mm: 0.8; SizeZ_mm: 1; EIA_Code: E192; U/M: EA; AEC Category: Q200
signal-integrity model Resistor
simulation model Resistor
footprint 0603
footprint 0603M
footprint 0603L
footprint 0603_HV
footprint 0603S
pins: 1, 2

## RT0603BRD0714K2L
designator R?  ValueDisplayed: 14.2k  (hidden comment: RT0603BRD0714K2L)
RES, 14.2 k, 0.1%, 0.1 W, 0603; Manufacturer: Yageo America; CompType: Resistor; Value: 14.2k; Res_ohm: 14200; Value_Code: 14k2; Tolerance_%: 0.1; Value2: 0.1W; VDC_V: 75; TempCo: 25 ppm/C; SizeArea_mm2: 1.28; SizeX_mm: 1.6; SizeY_mm: 0.8; SizeZ_mm: 1; EIA_Code: E192; U/M: EA; AEC Category: Q200
signal-integrity model Resistor
simulation model Resistor
footprint 0603
footprint 0603M
footprint 0603L
footprint 0603_HV
footprint 0603S
pins: 1, 2

## RT0603BRD0714K3L
designator R?  ValueDisplayed: 14.3k  (hidden comment: RT0603BRD0714K3L)
RES, 14.3 k, 0.1%, 0.1 W, 0603; Manufacturer: Yageo America; CompType: Resistor; Value: 14.3k; Res_ohm: 14300; Value_Code: 14k3; Tolerance_%: 0.1; Value2: 0.1W; VDC_V: 75; TempCo: 25 ppm/C; SizeArea_mm2: 1.28; SizeX_mm: 1.6; SizeY_mm: 0.8; SizeZ_mm: 1; EIA_Code: E192; U/M: EA; AEC Category: Q200
signal-integrity model Resistor
simulation model Resistor
footprint 0603
footprint 0603M
footprint 0603L
footprint 0603_HV
footprint 0603S
pins: 1, 2

## RT0603BRD0714K5L
designator R?  ValueDisplayed: 14.5k  (hidden comment: RT0603BRD0714K5L)
RES, 14.5 k, 0.1%, 0.1 W, 0603; Manufacturer: Yageo America; CompType: Resistor; Value: 14.5k; Res_ohm: 14500; Value_Code: 14k5; Tolerance_%: 0.1; Value2: 0.1W; VDC_V: 75; TempCo: 25 ppm/C; SizeArea_mm2: 1.28; SizeX_mm: 1.6; SizeY_mm: 0.8; SizeZ_mm: 1; EIA_Code: E192; U/M: EA; AEC Category: Q200
signal-integrity model Resistor
simulation model Resistor
footprint 0603
footprint 0603M
footprint 0603L
footprint 0603_HV
footprint 0603S
pins: 1, 2

## RT0603BRD0714K7L
designator R?  ValueDisplayed: 14.7k  (hidden comment: RT0603BRD0714K7L)
RES, 14.7 k, 0.1%, 0.1 W, 0603; Manufacturer: Yageo America; CompType: Resistor; Value: 14.7k; Res_ohm: 14700; Value_Code: 14k7; Tolerance_%: 0.1; Value2: 0.1W; VDC_V: 75; TempCo: 25 ppm/C; SizeArea_mm2: 1.28; SizeX_mm: 1.6; SizeY_mm: 0.8; SizeZ_mm: 1; EIA_Code: E192; U/M: EA; AEC Category: Q200
signal-integrity model Resistor
simulation model Resistor
footprint 0603
footprint 0603M
footprint 0603L
footprint 0603_HV
footprint 0603S
pins: 1, 2

## RT0603BRD0714K9L
designator R?  ValueDisplayed: 14.9k  (hidden comment: RT0603BRD0714K9L)
RES, 14.9 k, 0.1%, 0.1 W, 0603; Manufacturer: Yageo America; CompType: Resistor; Value: 14.9k; Res_ohm: 14900; Value_Code: 14k9; Tolerance_%: 0.1; Value2: 0.1W; VDC_V: 75; TempCo: 25 ppm/C; SizeArea_mm2: 1.28; SizeX_mm: 1.6; SizeY_mm: 0.8; SizeZ_mm: 1; EIA_Code: E192; U/M: EA; AEC Category: Q200
signal-integrity model Resistor
simulation model Resistor
footprint 0603
footprint 0603M
footprint 0603L
footprint 0603_HV
footprint 0603S
pins: 1, 2

## RT0603BRD0714KL
designator R?  ValueDisplayed: 14.0k  (hidden comment: RT0603BRD0714KL)
RES, 14.0 k, 0.1%, 0.1 W, 0603; Manufacturer: Yageo America; CompType: Resistor; Value: 14.0k; Res_ohm: 14000; Value_Code: 14k0; Tolerance_%: 0.1; Value2: 0.1W; VDC_V: 75; TempCo: 25 ppm/C; SizeArea_mm2: 1.28; SizeX_mm: 1.6; SizeY_mm: 0.8; SizeZ_mm: 1; EIA_Code: E192; U/M: EA; AEC Category: Q200
signal-integrity model Resistor
simulation model Resistor
footprint 0603
footprint 0603M
footprint 0603L
footprint 0603_HV
footprint 0603S
pins: 1, 2

## RT0603BRD0714R2L
designator R?  ValueDisplayed: 14.2  (hidden comment: RT0603BRD0714R2L)
RES, 14.2, 0.1%, 0.1 W, 0603; Manufacturer: Yageo America; CompType: Resistor; Value: 14.2; Value_Code: 14R2; Tolerance_%: 0.1; Value2: 0.1W; VDC_V: 75; TempCo: 25 ppm/C; SizeArea_mm2: 1.28; SizeX_mm: 1.6; SizeY_mm: 0.8; SizeZ_mm: 1; EIA_Code: E192; U/M: EA; AEC Category: Q200
signal-integrity model Resistor
simulation model Resistor
footprint 0603
footprint 0603M
footprint 0603L
footprint 0603_HV
footprint 0603S
pins: 1, 2

## RT0603BRD0714R3L
designator R?  ValueDisplayed: 14.3  (hidden comment: RT0603BRD0714R3L)
RES, 14.3, 0.1%, 0.1 W, 0603; Manufacturer: Yageo America; CompType: Resistor; Value: 14.3; Value_Code: 14R3; Tolerance_%: 0.1; Value2: 0.1W; VDC_V: 75; TempCo: 25 ppm/C; SizeArea_mm2: 1.28; SizeX_mm: 1.6; SizeY_mm: 0.8; SizeZ_mm: 1; EIA_Code: E192; U/M: EA; AEC Category: Q200
signal-integrity model Resistor
simulation model Resistor
footprint 0603
footprint 0603M
footprint 0603L
footprint 0603_HV
footprint 0603S
pins: 1, 2

## RT0603BRD0714R5L
designator R?  ValueDisplayed: 14.5  (hidden comment: RT0603BRD0714R5L)
RES, 14.5, 0.1%, 0.1 W, 0603; Manufacturer: Yageo America; CompType: Resistor; Value: 14.5; Value_Code: 14R5; Tolerance_%: 0.1; Value2: 0.1W; VDC_V: 75; TempCo: 25 ppm/C; SizeArea_mm2: 1.28; SizeX_mm: 1.6; SizeY_mm: 0.8; SizeZ_mm: 1; EIA_Code: E192; U/M: EA; AEC Category: Q200
signal-integrity model Resistor
simulation model Resistor
footprint 0603
footprint 0603M
footprint 0603L
footprint 0603_HV
footprint 0603S
pins: 1, 2

## RT0603BRD0714R7L
designator R?  ValueDisplayed: 14.7  (hidden comment: RT0603BRD0714R7L)
RES, 14.7, 0.1%, 0.1 W, 0603; Manufacturer: Yageo America; CompType: Resistor; Value: 14.7; Value_Code: 14R7; Tolerance_%: 0.1; Value2: 0.1W; VDC_V: 75; TempCo: 25 ppm/C; SizeArea_mm2: 1.28; SizeX_mm: 1.6; SizeY_mm: 0.8; SizeZ_mm: 1; EIA_Code: E192; U/M: EA; AEC Category: Q200
signal-integrity model Resistor
simulation model Resistor
footprint 0603
footprint 0603M
footprint 0603L
footprint 0603_HV
footprint 0603S
pins: 1, 2

## RT0603BRD0714R9L
designator R?  ValueDisplayed: 14.9  (hidden comment: RT0603BRD0714R9L)
RES, 14.9, 0.1%, 0.1 W, 0603; Manufacturer: Yageo America; CompType: Resistor; Value: 14.9; Value_Code: 14R9; Tolerance_%: 0.1; Value2: 0.1W; VDC_V: 75; TempCo: 25 ppm/C; SizeArea_mm2: 1.28; SizeX_mm: 1.6; SizeY_mm: 0.8; SizeZ_mm: 1; EIA_Code: E192; U/M: EA; AEC Category: Q200
signal-integrity model Resistor
simulation model Resistor
footprint 0603
footprint 0603M
footprint 0603L
footprint 0603_HV
footprint 0603S
pins: 1, 2

## RT0603BRD0714RL
designator R?  ValueDisplayed: 14.0  (hidden comment: RT0603BRD0714RL)
RES, 14.0, 0.1%, 0.1 W, 0603; Manufacturer: Yageo America; CompType: Resistor; Value: 14.0; Res_ohm: 14; Value_Code: 14R0; Tolerance_%: 0.1; Value2: 0.1W; VDC_V: 75; TempCo: 25 ppm/C; SizeArea_mm2: 1.28; SizeX_mm: 1.6; SizeY_mm: 0.8; SizeZ_mm: 1; EIA_Code: E192; U/M: EA; AEC Category: Q200
signal-integrity model Resistor
simulation model Resistor
footprint 0603
footprint 0603M
footprint 0603L
footprint 0603_HV
footprint 0603S
pins: 1, 2

## RT0603BRD0715K2L
designator R?  ValueDisplayed: 15.2k  (hidden comment: RT0603BRD0715K2L)
RES, 15.2 k, 0.1%, 0.1 W, 0603; Manufacturer: Yageo America; CompType: Resistor; Value: 15.2k; Res_ohm: 15200; Value_Code: 15k2; Tolerance_%: 0.1; Value2: 0.1W; VDC_V: 75; TempCo: 25 ppm/C; SizeArea_mm2: 1.28; SizeX_mm: 1.6; SizeY_mm: 0.8; SizeZ_mm: 1; EIA_Code: E192; U/M: EA; AEC Category: Q200
signal-integrity model Resistor
simulation model Resistor
footprint 0603
footprint 0603M
footprint 0603L
footprint 0603_HV
footprint 0603S
pins: 1, 2

## RT0603BRD0715K4L
designator R?  ValueDisplayed: 15.4k  (hidden comment: RT0603BRD0715K4L)
RES, 15.4 k, 0.1%, 0.1 W, 0603; Manufacturer: Yageo America; CompType: Resistor; Value: 15.4k; Res_ohm: 15400; Value_Code: 15k4; Tolerance_%: 0.1; Value2: 0.1W; VDC_V: 75; TempCo: 25 ppm/C; SizeArea_mm2: 1.28; SizeX_mm: 1.6; SizeY_mm: 0.8; SizeZ_mm: 1; EIA_Code: E192; U/M: EA; AEC Category: Q200
signal-integrity model Resistor
simulation model Resistor
footprint 0603
footprint 0603M
footprint 0603L
footprint 0603_HV
footprint 0603S
pins: 1, 2

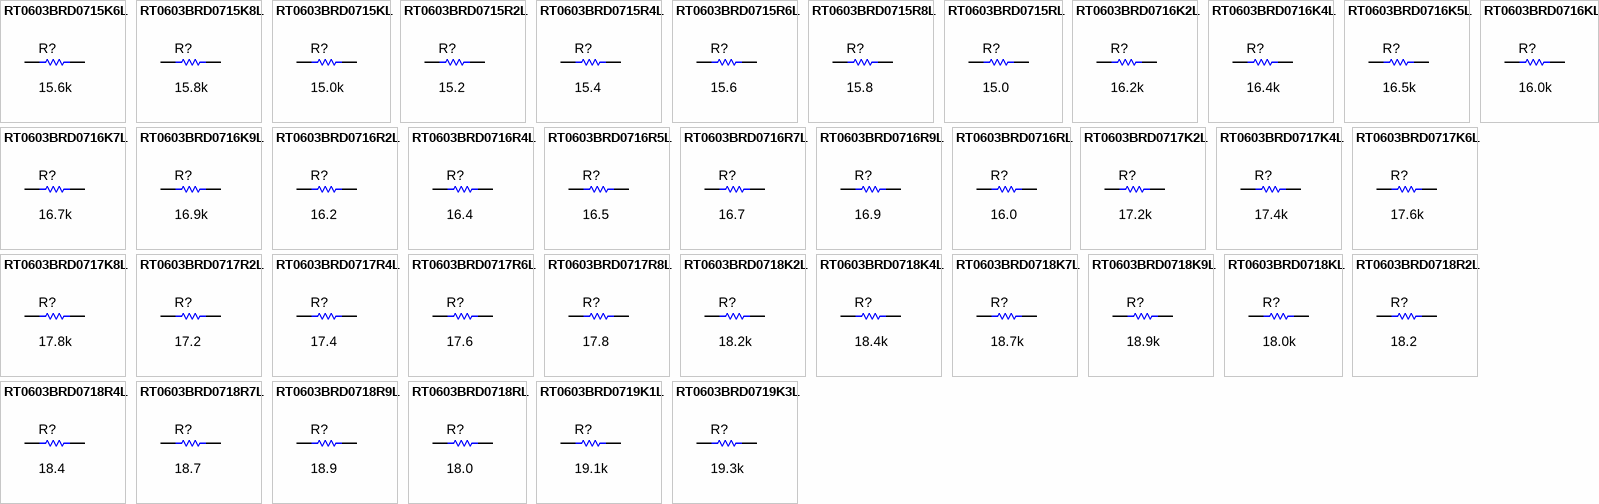
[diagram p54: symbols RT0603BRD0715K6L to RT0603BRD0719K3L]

## RT0603BRD0715K6L
designator R?  ValueDisplayed: 15.6k  (hidden comment: RT0603BRD0715K6L)
RES, 15.6 k, 0.1%, 0.1 W, 0603; Manufacturer: Yageo America; CompType: Resistor; Value: 15.6k; Res_ohm: 15600; Value_Code: 15k6; Tolerance_%: 0.1; Value2: 0.1W; VDC_V: 75; TempCo: 25 ppm/C; SizeArea_mm2: 1.28; SizeX_mm: 1.6; SizeY_mm: 0.8; SizeZ_mm: 1; EIA_Code: E192; U/M: EA; AEC Category: Q200
signal-integrity model Resistor
simulation model Resistor
footprint 0603
footprint 0603M
footprint 0603L
footprint 0603_HV
footprint 0603S
pins: 1, 2

## RT0603BRD0715K8L
designator R?  ValueDisplayed: 15.8k  (hidden comment: RT0603BRD0715K8L)
RES, 15.8 k, 0.1%, 0.1 W, 0603; Manufacturer: Yageo America; CompType: Resistor; Value: 15.8k; Res_ohm: 15800; Value_Code: 15k8; Tolerance_%: 0.1; Value2: 0.1W; VDC_V: 75; TempCo: 25 ppm/C; SizeArea_mm2: 1.28; SizeX_mm: 1.6; SizeY_mm: 0.8; SizeZ_mm: 1; EIA_Code: E192; U/M: EA; AEC Category: Q200
signal-integrity model Resistor
simulation model Resistor
footprint 0603
footprint 0603M
footprint 0603L
footprint 0603_HV
footprint 0603S
pins: 1, 2

## RT0603BRD0715KL
designator R?  ValueDisplayed: 15.0k  (hidden comment: RT0603BRD0715KL)
RES, 15.0 k, 0.1%, 0.1 W, 0603; Manufacturer: Yageo America; CompType: Resistor; Value: 15.0k; Res_ohm: 15000; Value_Code: 15k0; Tolerance_%: 0.1; Value2: 0.1W; VDC_V: 75; TempCo: 25 ppm/C; SizeArea_mm2: 1.28; SizeX_mm: 1.6; SizeY_mm: 0.8; SizeZ_mm: 1; EIA_Code: E192; U/M: EA; AEC Category: Q200; Green_Lifecycle: Active; Green_REACh: Passed
signal-integrity model Resistor
simulation model Resistor
footprint 0603
footprint 0603M
footprint 0603L
footprint 0603_HV
footprint 0603S
pins: 1, 2

## RT0603BRD0715R2L
designator R?  ValueDisplayed: 15.2  (hidden comment: RT0603BRD0715R2L)
RES, 15.2, 0.1%, 0.1 W, 0603; Manufacturer: Yageo America; CompType: Resistor; Value: 15.2; Value_Code: 15R2; Tolerance_%: 0.1; Value2: 0.1W; VDC_V: 75; TempCo: 25 ppm/C; SizeArea_mm2: 1.28; SizeX_mm: 1.6; SizeY_mm: 0.8; SizeZ_mm: 1; EIA_Code: E192; U/M: EA; AEC Category: Q200
signal-integrity model Resistor
simulation model Resistor
footprint 0603
footprint 0603M
footprint 0603L
footprint 0603_HV
footprint 0603S
pins: 1, 2

## RT0603BRD0715R4L
designator R?  ValueDisplayed: 15.4  (hidden comment: RT0603BRD0715R4L)
RES, 15.4, 0.1%, 0.1 W, 0603; Manufacturer: Yageo America; CompType: Resistor; Value: 15.4; Value_Code: 15R4; Tolerance_%: 0.1; Value2: 0.1W; VDC_V: 75; TempCo: 25 ppm/C; SizeArea_mm2: 1.28; SizeX_mm: 1.6; SizeY_mm: 0.8; SizeZ_mm: 1; EIA_Code: E192; U/M: EA; AEC Category: Q200
signal-integrity model Resistor
simulation model Resistor
footprint 0603
footprint 0603M
footprint 0603L
footprint 0603_HV
footprint 0603S
pins: 1, 2

## RT0603BRD0715R6L
designator R?  ValueDisplayed: 15.6  (hidden comment: RT0603BRD0715R6L)
RES, 15.6, 0.1%, 0.1 W, 0603; Manufacturer: Yageo America; CompType: Resistor; Value: 15.6; Value_Code: 15R6; Tolerance_%: 0.1; Value2: 0.1W; VDC_V: 75; TempCo: 25 ppm/C; SizeArea_mm2: 1.28; SizeX_mm: 1.6; SizeY_mm: 0.8; SizeZ_mm: 1; EIA_Code: E192; U/M: EA; AEC Category: Q200
signal-integrity model Resistor
simulation model Resistor
footprint 0603
footprint 0603M
footprint 0603L
footprint 0603_HV
footprint 0603S
pins: 1, 2

## RT0603BRD0715R8L
designator R?  ValueDisplayed: 15.8  (hidden comment: RT0603BRD0715R8L)
RES, 15.8, 0.1%, 0.1 W, 0603; Manufacturer: Yageo America; CompType: Resistor; Value: 15.8; Value_Code: 15R8; Tolerance_%: 0.1; Value2: 0.1W; VDC_V: 75; TempCo: 25 ppm/C; SizeArea_mm2: 1.28; SizeX_mm: 1.6; SizeY_mm: 0.8; SizeZ_mm: 1; EIA_Code: E192; U/M: EA; AEC Category: Q200
signal-integrity model Resistor
simulation model Resistor
footprint 0603
footprint 0603M
footprint 0603L
footprint 0603_HV
footprint 0603S
pins: 1, 2

## RT0603BRD0715RL
designator R?  ValueDisplayed: 15.0  (hidden comment: RT0603BRD0715RL)
RES, 15.0, 0.1%, 0.1 W, 0603; Manufacturer: Yageo America; CompType: Resistor; Value: 15.0; Res_ohm: 15; Value_Code: 15R0; Tolerance_%: 0.1; Value2: 0.1W; VDC_V: 75; TempCo: 25 ppm/C; SizeArea_mm2: 1.28; SizeX_mm: 1.6; SizeY_mm: 0.8; SizeZ_mm: 1; EIA_Code: E192; U/M: EA; AEC Category: Q200; Green_Lifecycle: Active; Green_REACh: Passed
signal-integrity model Resistor
simulation model Resistor
footprint 0603
footprint 0603M
footprint 0603L
footprint 0603_HV
footprint 0603S
pins: 1, 2

## RT0603BRD0716K2L
designator R?  ValueDisplayed: 16.2k  (hidden comment: RT0603BRD0716K2L)
RES, 16.2 k, 0.1%, 0.1 W, 0603; Manufacturer: Yageo America; CompType: Resistor; Value: 16.2k; Res_ohm: 16200; Value_Code: 16k2; Tolerance_%: 0.1; Value2: 0.1W; VDC_V: 75; TempCo: 25 ppm/C; SizeArea_mm2: 1.28; SizeX_mm: 1.6; SizeY_mm: 0.8; SizeZ_mm: 1; EIA_Code: E192; U/M: EA; AEC Category: Q200
signal-integrity model Resistor
simulation model Resistor
footprint 0603
footprint 0603M
footprint 0603L
footprint 0603_HV
footprint 0603S
pins: 1, 2

## RT0603BRD0716K4L
designator R?  ValueDisplayed: 16.4k  (hidden comment: RT0603BRD0716K4L)
RES, 16.4 k, 0.1%, 0.1 W, 0603; Manufacturer: Yageo America; CompType: Resistor; Value: 16.4k; Res_ohm: 16400; Value_Code: 16k4; Tolerance_%: 0.1; Value2: 0.1W; VDC_V: 75; TempCo: 25 ppm/C; SizeArea_mm2: 1.28; SizeX_mm: 1.6; SizeY_mm: 0.8; SizeZ_mm: 1; EIA_Code: E192; U/M: EA; AEC Category: Q200
signal-integrity model Resistor
simulation model Resistor
footprint 0603
footprint 0603M
footprint 0603L
footprint 0603_HV
footprint 0603S
pins: 1, 2

## RT0603BRD0716K5L
designator R?  ValueDisplayed: 16.5k  (hidden comment: RT0603BRD0716K5L)
RES, 16.5 k, 0.1%, 0.1 W, 0603; Manufacturer: Yageo America; CompType: Resistor; Value: 16.5k; Res_ohm: 16500; Value_Code: 16k5; Tolerance_%: 0.1; Value2: 0.1W; VDC_V: 75; TempCo: 25 ppm/C; SizeArea_mm2: 1.28; SizeX_mm: 1.6; SizeY_mm: 0.8; SizeZ_mm: 1; EIA_Code: E192; U/M: EA; AEC Category: Q200
signal-integrity model Resistor
simulation model Resistor
footprint 0603
footprint 0603M
footprint 0603L
footprint 0603_HV
footprint 0603S
pins: 1, 2

## RT0603BRD0716K7L
designator R?  ValueDisplayed: 16.7k  (hidden comment: RT0603BRD0716K7L)
RES, 16.7 k, 0.1%, 0.1 W, 0603; Manufacturer: Yageo America; CompType: Resistor; Value: 16.7k; Res_ohm: 16700; Value_Code: 16k7; Tolerance_%: 0.1; Value2: 0.1W; VDC_V: 75; TempCo: 25 ppm/C; SizeArea_mm2: 1.28; SizeX_mm: 1.6; SizeY_mm: 0.8; SizeZ_mm: 1; EIA_Code: E192; U/M: EA; AEC Category: Q200
signal-integrity model Resistor
simulation model Resistor
footprint 0603
footprint 0603M
footprint 0603L
footprint 0603_HV
footprint 0603S
pins: 1, 2

## RT0603BRD0716K9L
designator R?  ValueDisplayed: 16.9k  (hidden comment: RT0603BRD0716K9L)
RES, 16.9 k, 0.1%, 0.1 W, 0603; Manufacturer: Yageo America; CompType: Resistor; Value: 16.9k; Res_ohm: 16900; Value_Code: 16k9; Tolerance_%: 0.1; Value2: 0.1W; VDC_V: 75; TempCo: 25 ppm/C; SizeArea_mm2: 1.28; SizeX_mm: 1.6; SizeY_mm: 0.8; SizeZ_mm: 1; EIA_Code: E192; U/M: EA; AEC Category: Q200
signal-integrity model Resistor
simulation model Resistor
footprint 0603
footprint 0603M
footprint 0603L
footprint 0603_HV
footprint 0603S
pins: 1, 2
